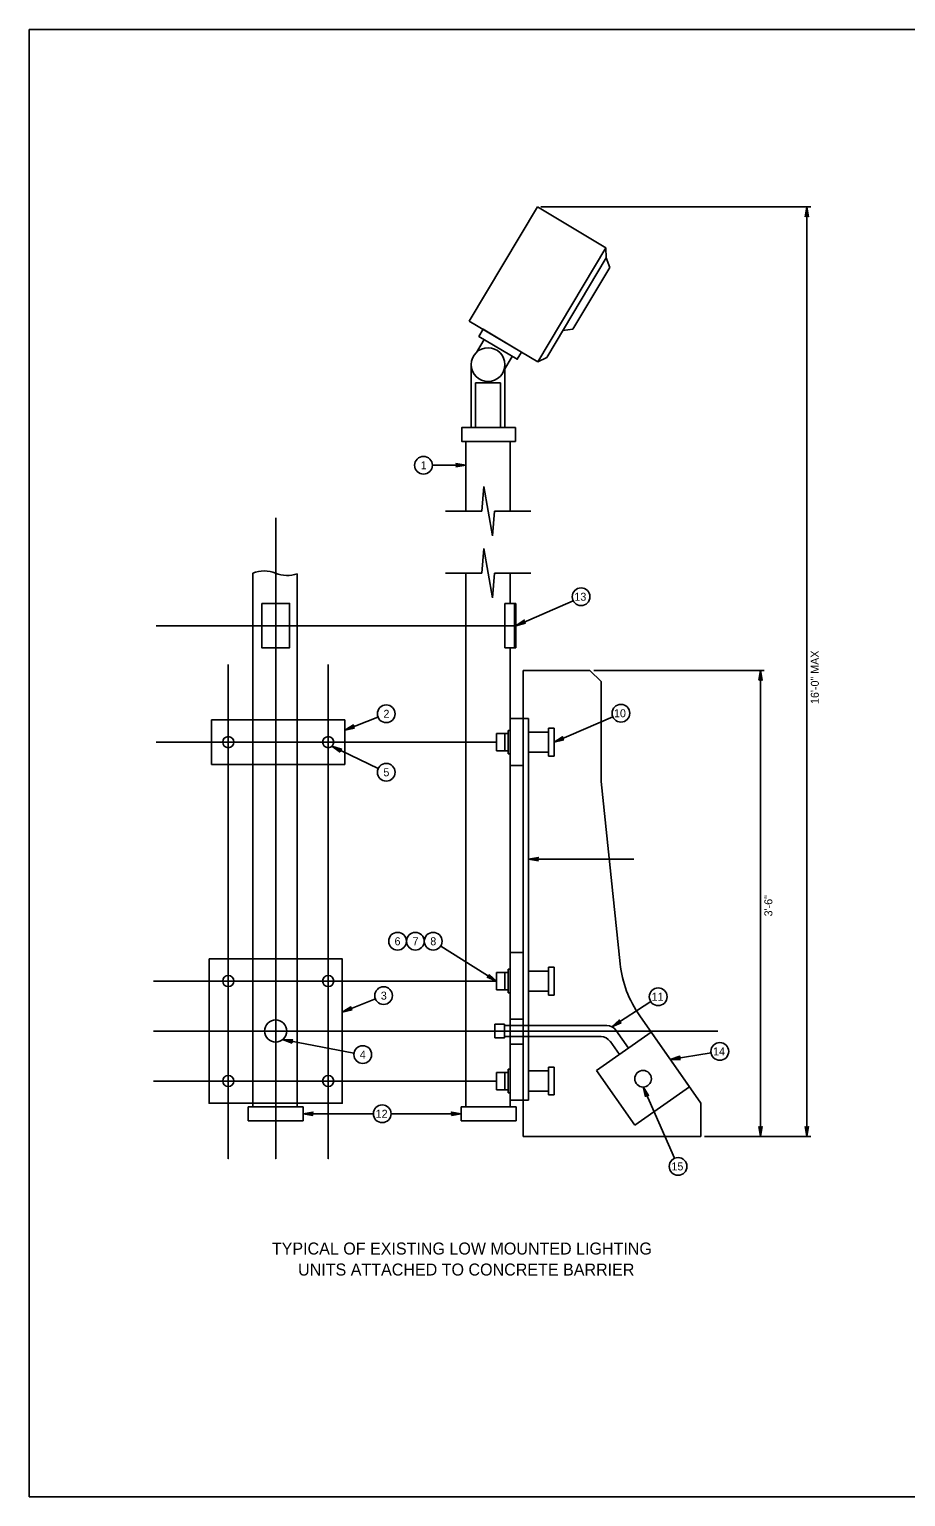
# Model space of a CAD drawing. Extents: x 99968 to 128667, y 90163 to 102182.
# Drawn here: x 99968 to 101281, y 90267 to 92467 of the extents above; entities that cross this region are included whole.
import ezdxf

# ---------------------------------------------------------------- set-up
doc = ezdxf.new("R2010")
doc.units = 0
doc.layers.add('Default', color=7, linetype='Continuous')
doc.layers.add('RD Standard Plans Active', color=7, linetype='Continuous')

msp = doc.modelspace()

# ---------------------------------------------------------------- linework, layer by layer
at = {"layer": 'Default'}
msp.add_lwpolyline([(99967.5, 92466.5), (103167.2, 92466.5), (103167.2, 90266.9), (99967.5, 90266.9)], close=True, dxfattribs=at)
at = {"layer": 'RD Standard Plans Active'}
for p, q in [((100627.1, 92029.3), (100729.3, 92200.4)), ((100729.3, 92200.4), (100831.9, 92139.1)), ((101138.8, 92200.4), (100734.3, 92200.4)), ((101133, 90806.7), (101133, 92200.4)), ((100729.8, 91968), (100831.9, 92139.1)), ((100832.3, 92124.1), (100743.2, 91974.8)), ((100831.9, 92139.1), (100832.3, 92124.1)), ((100832.3, 92124.1), (100837.7, 92109.6)), ((100837.7, 92109.6), (100782.4, 92016.9)), ((100627.1, 92029.3), (100729.8, 91968)), ((100767.1, 92014.9), (100782.4, 92016.9)), ((100649.3, 92001.5), (100637.7, 91982.1)), ((100691.5, 91976.3), (100678.9, 91955.1)), ((100729.8, 91968), (100743.2, 91974.8)), ((100629.9, 91869.6), (100629.9, 91963.9)), ((100680.1, 91869.6), (100680.1, 91957.2)), ((100673.8, 91936.6), (100636.2, 91936.6)), ((100636.2, 91936.6), (100636.2, 91869.6)), ((100673.8, 91869.6), (100673.8, 91936.6)), ((100621.9, 91848.8), (100688.5, 91848.8)), ((100621.9, 91848.8), (100621.9, 91744.3)), ((100688.5, 91848.8), (100688.5, 91744.3)), ((100571.8, 91813), (100621.9, 91813)), ((100645.7, 91744.3), (100648.7, 91781.2)), ((100648.7, 91781.2), (100661.7, 91707.5)), ((100591.2, 91744.3), (100645.7, 91744.3)), ((100664.7, 91744.3), (100661.7, 91707.5)), ((100664.7, 91744.3), (100719.2, 91744.3)), ((100645.7, 91651.2), (100648.7, 91688.1)), ((100648.7, 91688.1), (100661.7, 91614.3)), ((100302.4, 91651.2), (100302.4, 90851.4)), ((100369, 91650.4), (100369, 90851.4)), ((100591.2, 91651.2), (100645.7, 91651.2)), ((100621.9, 91651.2), (100621.9, 90851.4)), ((100664.7, 91651.2), (100661.7, 91614.3)), ((100664.7, 91651.2), (100719.2, 91651.2)), ((100688.5, 91651.2), (100688.5, 91605.9)), ((100696.8, 91605.9), (100680.2, 91605.9)), ((100680.2, 91605.9), (100680.2, 91539.4)), ((100694.7, 91605.9), (100694.7, 91539.4)), ((100696.8, 91572.6), (100782.6, 91609.8)), ((100696.8, 91605.9), (100696.8, 91539.4)), ((100696.8, 91539.4), (100680.2, 91539.4)), ((100688.5, 91539.4), (100688.5, 90851.4)), ((100807.9, 91505.6), (100708, 91505.6)), ((100708, 90806.7), (100708, 91505.6)), ((100824.5, 91489), (100807.9, 91505.6)), ((101069.2, 91505.6), (100813.9, 91505.6)), ((101063.4, 90806.7), (101063.4, 91505.6)), ((100824.5, 91339.2), (100824.5, 91489)), ((100440.4, 91415.8), (100490.1, 91435.6)), ((100685.2, 91411), (100685.2, 91415.7)), ((100685.2, 91415.7), (100688.5, 91415.7)), ((100688.5, 91433.2), (100708, 91433.2)), ((100708, 91433.2), (100715.7, 91433.2)), ((100715.7, 91433.2), (100715.7, 90861.2)), ((100745.7, 91413.1), (100745.7, 91418.9)), ((100745.7, 91418.9), (100754.3, 91418.9)), ((100754.3, 91398), (100842.2, 91436)), ((100754.3, 91418.9), (100754.3, 91377.1)), ((100668, 91411), (100668, 91385)), ((100680.4, 91411), (100668, 91411)), ((100680.4, 91385), (100680.4, 91411)), ((100680.4, 91411), (100685.2, 91411)), ((100685.2, 91411), (100685.2, 91385)), ((100715.7, 91413.1), (100745.7, 91413.1)), ((100745.7, 91413.1), (100745.7, 91377.1)), ((100421.1, 91391.9), (100490.4, 91358.6)), ((100668, 91385), (100680.4, 91385)), ((100680.4, 91385), (100685.2, 91385)), ((100685.2, 91385), (100685.2, 91380.3)), ((100685.2, 91380.3), (100688.5, 91380.3)), ((100715.7, 91382.9), (100745.7, 91382.9)), ((100745.7, 91377.1), (100754.3, 91377.1)), ((100688.5, 91362.8), (100708, 91362.8)), ((100824.5, 91339.2), (100853.3, 91065.8)), ((100715.7, 91222.6), (100873.5, 91222.6)), ((100668, 91039.8), (100584.2, 91092.4)), ((100688.5, 91082.5), (100708, 91082.5)), ((100668, 91052.8), (100668, 91026.8)), ((100680.4, 91052.8), (100668, 91052.8)), ((100680.4, 91026.8), (100680.4, 91052.8)), ((100680.4, 91052.8), (100685.2, 91052.8)), ((100685.2, 91052.8), (100685.2, 91057.5)), ((100685.2, 91057.5), (100688.5, 91057.5)), ((100685.2, 91052.8), (100685.2, 91026.8)), ((100715.7, 91054.9), (100745.7, 91054.9)), ((100745.7, 91054.9), (100745.7, 91060.7)), ((100745.7, 91060.7), (100754.3, 91060.7)), ((100745.7, 91054.9), (100745.7, 91018.9)), ((100754.3, 91060.7), (100754.3, 91018.9)), ((100668, 91026.8), (100680.4, 91026.8)), ((100680.4, 91026.8), (100685.2, 91026.8)), ((100685.2, 91026.8), (100685.2, 91022.1)), ((100685.2, 91022.1), (100688.5, 91022.1)), ((100715.7, 91024.7), (100745.7, 91024.7)), ((100436.6, 90993.3), (100486.2, 91013.1)), ((100745.7, 91018.9), (100754.3, 91018.9)), ((100840.9, 90971.3), (100899, 91009.1)), ((100688.5, 90982.7), (100708, 90982.7)), ((100974.3, 90856.6), (100882.5, 90987.8)), ((100665.2, 90975.2), (100665.2, 90954.6)), ((100679.7, 90973.2), (100833.2, 90973.2)), ((100679.7, 90956.6), (100824.5, 90956.6)), ((100899.7, 90963.1), (100817.9, 90905.8)), ((100846.8, 90966.1), (100865.7, 90939.2)), ((100899.7, 90963.1), (100957, 90881.3)), ((100347.2, 90952), (100454.2, 90932)), ((100688.5, 90945.2), (100708, 90945.2)), ((100838.2, 90949.5), (100852, 90929.7)), ((100928.4, 90922.2), (100989.5, 90932.3)), ((100745.7, 90905.1), (100745.7, 90910.9)), ((100745.7, 90910.9), (100754.3, 90910.9)), ((100754.3, 90910.9), (100754.3, 90869.1)), ((100668, 90903), (100668, 90877)), ((100680.4, 90903), (100668, 90903)), ((100680.4, 90877), (100680.4, 90903)), ((100680.4, 90903), (100685.2, 90903)), ((100685.2, 90903), (100685.2, 90907.7)), ((100685.2, 90907.7), (100688.5, 90907.7)), ((100685.2, 90903), (100685.2, 90877)), ((100715.7, 90905.1), (100745.7, 90905.1)), ((100745.7, 90905.1), (100745.7, 90869.1)), ((100817.9, 90905.8), (100875.2, 90824)), ((100668, 90877), (100680.4, 90877)), ((100680.4, 90877), (100685.2, 90877)), ((100685.2, 90877), (100685.2, 90872.3)), ((100685.2, 90872.3), (100688.5, 90872.3)), ((100715.7, 90874.9), (100745.7, 90874.9)), ((100745.7, 90869.1), (100754.3, 90869.1)), ((100957, 90881.3), (100875.2, 90824)), ((100887.5, 90881.1), (100934.6, 90774.2)), ((100295.7, 90851.4), (100377.8, 90851.4)), ((100295.7, 90830.5), (100295.7, 90851.4)), ((100377.8, 90851.4), (100377.8, 90830.5)), ((100615.1, 90851.4), (100697.3, 90851.4)), ((100615.1, 90830.5), (100615.1, 90851.4)), ((100708, 90861.2), (100688.5, 90861.2)), ((100697.3, 90851.4), (100697.3, 90830.5)), ((100715.7, 90861.2), (100708, 90861.2)), ((100974.3, 90856.6), (100974.3, 90806.7)), ((100377.8, 90830.5), (100295.7, 90830.5)), ((100377.8, 90840.9), (100483.2, 90840.9)), ((100509.8, 90840.9), (100615.1, 90840.9)), ((100697.3, 90830.5), (100615.1, 90830.5)), ((100974.3, 90806.7), (100708, 90806.7)), ((100966, 90806.7), (100966, 90806.7)), ((101138.8, 90806.7), (100979.4, 90806.7))]:
    msp.add_line(p, q, dxfattribs=at)
for points in [[(101130.4, 92185.5), (101133, 92200.4), (101135.5, 92185.5), (101133, 92187.8)], [(100705.3, 91982.6), (100647.8, 92016.9), (100641.4, 92006.2), (100698.9, 91971.9)], [(100688.5, 91848.8), (100696.1, 91848.8), (100696.1, 91869.6), (100615.7, 91869.6), (100615.7, 91848.8)], [(100607, 91810.5), (100621.9, 91813), (100607, 91815.5), (100609.4, 91813)], [(100316, 91605.9), (100357.6, 91605.9), (100357.6, 91539.4), (100316, 91539.4)], [(100711.5, 91576.2), (100696.8, 91572.6), (100709.5, 91580.9), (100708.3, 91577.6)], [(101060.9, 91490.7), (101063.4, 91505.6), (101065.9, 91490.7), (101063.4, 91493)], [(100240.7, 91431.3), (100440.4, 91431.3), (100440.4, 91364.7), (100240.7, 91364.7)], [(100455.2, 91419), (100440.4, 91415.8), (100453.3, 91423.7), (100452.1, 91420.5)], [(100769, 91401.6), (100754.3, 91398), (100767, 91406.2), (100765.8, 91403)], [(100433.5, 91383.2), (100421.1, 91391.9), (100435.7, 91387.7), (100432.5, 91386.5)], [(100730.6, 91220.1), (100715.7, 91222.6), (100730.6, 91225.1), (100728.2, 91222.6)], [(100236.9, 91073.1), (100436.6, 91073.1), (100436.6, 90856.7), (100236.9, 90856.7)], [(100656.7, 91049.9), (100668, 91039.8), (100654, 91045.6), (100657.4, 91046.5)], [(100451.4, 90996.5), (100436.6, 90993.3), (100449.5, 91001.2), (100448.3, 90998)], [(100854.8, 90977.3), (100840.9, 90971.3), (100852, 90981.6), (100851.4, 90978.2)], [(100361.4, 90946.8), (100347.2, 90952), (100362.3, 90951.7), (100359.6, 90949.7)], [(100943.5, 90922.1), (100928.4, 90922.2), (100942.7, 90927.1), (100940.8, 90924.2)], [(100891.2, 90866.4), (100887.5, 90881.1), (100895.8, 90868.4), (100892.5, 90869.6)], [(100392.7, 90838.4), (100377.8, 90840.9), (100392.7, 90843.4), (100390.4, 90840.9)], [(100600.2, 90838.4), (100615.1, 90840.9), (100600.2, 90843.4), (100602.6, 90840.9)], [(101060.9, 90821.6), (101063.4, 90806.7), (101065.9, 90821.6), (101063.4, 90819.2)], [(101130.4, 90821.6), (101133, 90806.7), (101135.5, 90821.6), (101133, 90819.2)]]:
    msp.add_lwpolyline(points, close=True, dxfattribs=at)
for points in [[(100336.8, 90856.7), (100336.8, 90773.5), (100336.8, 91734.4)], [(100696.8, 91572.6), (100157.5, 91572.6)], [(100265.7, 90865.1), (100265.7, 90773.5), (100265.7, 91514.5)], [(100415.5, 90865.1), (100415.5, 90773.5), (100415.5, 91514.5)], [(100668, 91398), (100157.5, 91398)], [(100668, 91039.8), (100153.7, 91039.8)], [(100999.8, 90964.9), (100153.7, 90964.9)], [(100679.7, 90964.9), (100679.7, 90975.2), (100665.2, 90975.2)], [(100679.7, 90964.9), (100679.7, 90954.6), (100665.2, 90954.6)], [(100668, 90890), (100153.7, 90890)]]:
    msp.add_lwpolyline(points, dxfattribs=at)
for centre, radius in [((100655.2, 91963.9), 25.3), ((100558.4, 91813), 13.3), ((100794.6, 91616), 13.3), ((100502.5, 91440.5), 13.3), ((100854.4, 91441.3), 13.3), ((100265.7, 91398), 8.32), ((100415.5, 91398), 8.32), ((100502.5, 91352.8), 13.3), ((100519.5, 91099.5), 13.3), ((100546.2, 91099.5), 13.3), ((100572.9, 91099.5), 13.3), ((100265.7, 91039.8), 8.32), ((100415.5, 91039.8), 8.32), ((100498.6, 91018), 13.3), ((100910.2, 91016.3), 13.3), ((100336.8, 90964.9), 16.6), ((100467.3, 90929.6), 13.3), ((101002.6, 90934.4), 13.3), ((100265.7, 90890), 8.32), ((100415.5, 90890), 8.32), ((100887.5, 90893.5), 12.5), ((100496.5, 90840.9), 13.3), ((100940, 90762), 13.3)]:
    msp.add_circle(centre, radius, dxfattribs=at)
for centre, radius, start, end in [((100319.6, 91608.8), 45.8, 67.9809, 112.0191), ((100353.9, 91693.6), 45.8, 247.9809, 289.2679), ((101018.8, 91083.2), 166.4, 186.0091, 214.992), ((100824.5, 90939.9), 16.6, 34.992, 90), ((100833.2, 90956.6), 16.6, 34.992, 90)]:
    msp.add_arc(centre, radius, start, end, dxfattribs=at)

# ---------------------------------------------------------------- texts
for s, height, p in [('1', 12, (100554.2, 91807)), ('13', 12, (100784.6, 91610)), ('2', 12, (100498.4, 91434.5)), ('10', 12, (100844, 91435.3)), ('5', 12, (100498.3, 91346.8)), ('6', 12, (100515, 91093.5)), ('7', 12, (100542, 91093.5)), ('8', 12, (100568.6, 91093.5)), ('3', 12, (100494.4, 91012)), ('11', 12, (100900.3, 91010.3)), ('4', 12, (100462.9, 90923.6)), ('14', 12, (100992.5, 90928.4)), ('12', 12, (100486.7, 90834.9)), ('15', 12, (100930.1, 90756)), ('TYPICAL OF EXISTING LOW MOUNTED LIGHTING', 18, (100331.1, 90629.9)), ('UNITS ATTACHED TO CONCRETE BARRIER', 18, (100370.4, 90598.4))]:
    msp.add_text(s, height=height, dxfattribs=at).set_placement(p)
for s, p in [('16\'-0" MAX', (101151, 91455.2)), ('3\'-6"', (101081.4, 91136.8))]:
    msp.add_text(s, height=12, rotation=90, dxfattribs=at).set_placement(p)

doc.saveas('drawing.dxf')
